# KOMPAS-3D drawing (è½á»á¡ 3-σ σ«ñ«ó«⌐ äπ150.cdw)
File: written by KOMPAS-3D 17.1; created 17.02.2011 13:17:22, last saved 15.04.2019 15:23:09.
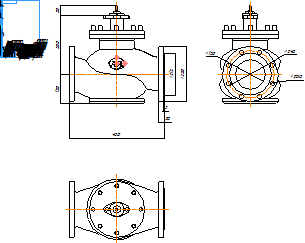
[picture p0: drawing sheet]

Title block, sheet 1: name: Клапан 3-х ходовой Ду150; material: Внимание! Данный продукт является объектом авторского права ООО «Торговый Дом АДЛ». / Запрещается изменение, копирование, распространение / (в том числе путем копирования на другие сайты и ресурсы в Интернете) / или любое иное использование информации и объектов без предварительного / согласия правообладателя (ООО «Торговый Дом АДЛ»).; scale: 1:1; sheets: 1; organisation: ООО "Торговый дом АДЛ"; sheet format: A4; stored path: \\adlc.lan\data\АДЛ_ПКД\3D-модели\ADL production\Клапаны ГРАНРЕГ\Трёхходовой клапан КМ307Ф\KOMPAS 2D\Клапан 3-х ходовой Ду150.cdw

Views: Спереди 1, Проекционный вид 2, Проекционный вид 3
Dimensions and other numbers on the sheet: 480; 150; 300; 50; 240; 22; 3; 28; 212; 280; 1:1; 1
